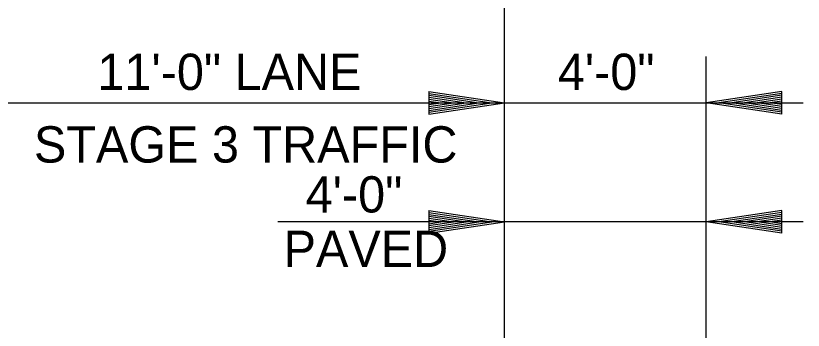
# Model space of a CAD drawing. Extents: x 1807779 to 1818251, y 673292 to 678849.
# Drawn here: x 1817284.3 to 1817440.5, y 674017.4 to 674079.8 of the extents above; entities that cross this region are included whole.
import ezdxf

# ---------------------------------------------------------------- set-up
doc = ezdxf.new("R2010")
doc.units = 0
doc.layers.add('Dimensions', color=7, linetype='Continuous')

msp = doc.modelspace()

# ---------------------------------------------------------------- linework, layer by layer
at = {"layer": 'Dimensions'}
for p, q in [((1817381.27, 673938.29), (1817381.27, 674132.54)), ((1817421.27, 673978.67), (1817421.27, 674071.72)), ((1817366.27, 674064.76), (1817381.27, 674062.51)), ((1817366.27, 674064.76), (1817366.27, 674060.26)), ((1817366.27, 674064.38), (1817378.76, 674062.51)), ((1817366.27, 674064), (1817376.18, 674062.51)), ((1817366.27, 674063.63), (1817373.68, 674062.51)), ((1817436.27, 674064.76), (1817421.27, 674062.51)), ((1817436.27, 674064.38), (1817423.77, 674062.51)), ((1817436.27, 674064), (1817426.35, 674062.51)), ((1817436.27, 674063.63), (1817428.85, 674062.51)), ((1817436.27, 674060.26), (1817436.27, 674064.76)), ((1817271.27, 674062.51), (1817381.27, 674062.51)), ((1817366.27, 674063.24), (1817371.14, 674062.51)), ((1817366.27, 674062.86), (1817368.64, 674062.51)), ((1817366.27, 674060.26), (1817381.27, 674062.51)), ((1817366.27, 674061.77), (1817371.14, 674062.51)), ((1817366.27, 674061.02), (1817376.18, 674062.51)), ((1817366.27, 674060.63), (1817378.76, 674062.51)), ((1817366.27, 674061.39), (1817373.68, 674062.51)), ((1817366.27, 674062.16), (1817368.64, 674062.51)), ((1817381.27, 674062.51), (1817440.51, 674062.51)), ((1817436.27, 674060.26), (1817421.27, 674062.51)), ((1817436.27, 674060.63), (1817423.77, 674062.51)), ((1817436.27, 674061.02), (1817426.35, 674062.51)), ((1817436.27, 674061.39), (1817428.85, 674062.51)), ((1817436.27, 674063.24), (1817431.39, 674062.51)), ((1817436.27, 674061.78), (1817431.39, 674062.51)), ((1817436.27, 674062.86), (1817433.9, 674062.51)), ((1817436.27, 674062.16), (1817433.9, 674062.51)), ((1817366.27, 674041.14), (1817381.27, 674038.89)), ((1817366.27, 674041.14), (1817366.27, 674036.64)), ((1817366.27, 674040.77), (1817378.76, 674038.89)), ((1817366.27, 674040.39), (1817376.18, 674038.89)), ((1817366.27, 674040.01), (1817373.68, 674038.89)), ((1817436.27, 674041.14), (1817421.27, 674038.89)), ((1817436.27, 674040.77), (1817423.77, 674038.89)), ((1817436.27, 674040.39), (1817426.35, 674038.89)), ((1817436.27, 674040.01), (1817428.85, 674038.89)), ((1817436.27, 674036.64), (1817436.27, 674041.14)), ((1817440.51, 674038.89), (1817336.31, 674038.89)), ((1817366.27, 674039.62), (1817371.14, 674038.89)), ((1817366.27, 674039.25), (1817368.64, 674038.89)), ((1817366.27, 674036.64), (1817381.27, 674038.89)), ((1817366.27, 674038.16), (1817371.14, 674038.89)), ((1817366.27, 674037.4), (1817376.18, 674038.89)), ((1817366.27, 674037.02), (1817378.76, 674038.89)), ((1817366.27, 674037.78), (1817373.68, 674038.89)), ((1817366.27, 674038.54), (1817368.64, 674038.89)), ((1817436.27, 674036.64), (1817421.27, 674038.89)), ((1817436.27, 674037.02), (1817423.77, 674038.89)), ((1817436.27, 674037.4), (1817426.35, 674038.89)), ((1817436.27, 674037.78), (1817428.85, 674038.89)), ((1817436.27, 674039.63), (1817431.39, 674038.89)), ((1817436.27, 674038.17), (1817431.39, 674038.89)), ((1817436.27, 674039.25), (1817433.9, 674038.89)), ((1817436.27, 674038.54), (1817433.9, 674038.89))]:
    msp.add_line(p, q, dxfattribs=at)

# ---------------------------------------------------------------- texts
for s, p in [('11\'-0" LANE', (1817300.55, 674065.06)), ('4\'-0"', (1817391.85, 674065.06)), ('STAGE 3 TRAFFIC', (1817287.95, 674050.66)), ('4\'-0"', (1817341.84, 674040.75)), ('PAVED', (1817337.46, 674029.95))]:
    msp.add_text(s, height=7.2, dxfattribs=at).set_placement(p)

doc.saveas('drawing.dxf')
